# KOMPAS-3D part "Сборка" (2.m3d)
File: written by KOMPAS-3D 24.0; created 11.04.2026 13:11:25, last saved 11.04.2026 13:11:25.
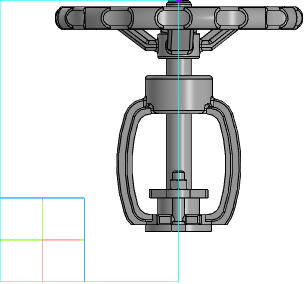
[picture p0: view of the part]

Document properties: Автор: R2D2; Полное имя файла: E:\Работа\Зайцев\VSO3131M-F-S Клапан запорный DN.ru Ду15-100 Ру40\DN25\исходные материалы\2.m3d

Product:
- Body: Тело 2  | qty 1
    Масса: 1.430783
- Part/product: Сборка
    Масса: 1.450691

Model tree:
1. Операция без истории:1
2. Точка:1  (with: Грань.Операция без истории:1)
     X = 81.2608; Y = 142.75; Z = 30
3. Параллельная плоскость:1
4. Эскиз:3  (with: Вершина.Операция без истории:1, Ребро.Операция без истории:1)
5. Элемент вращения:2
     Угол 1 = 360
6. Эскиз:4  (with: Ребро.Операция без истории:1)
7. Элемент выдавливания:1
     Расстояние 1 = 27
8. Параллельная плоскость:2
9. Зеркальный массив:1
10. Экземпляр ( 1 )
11. Экземпляр ( 2 )  (with: Элемент выдавливания:1)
